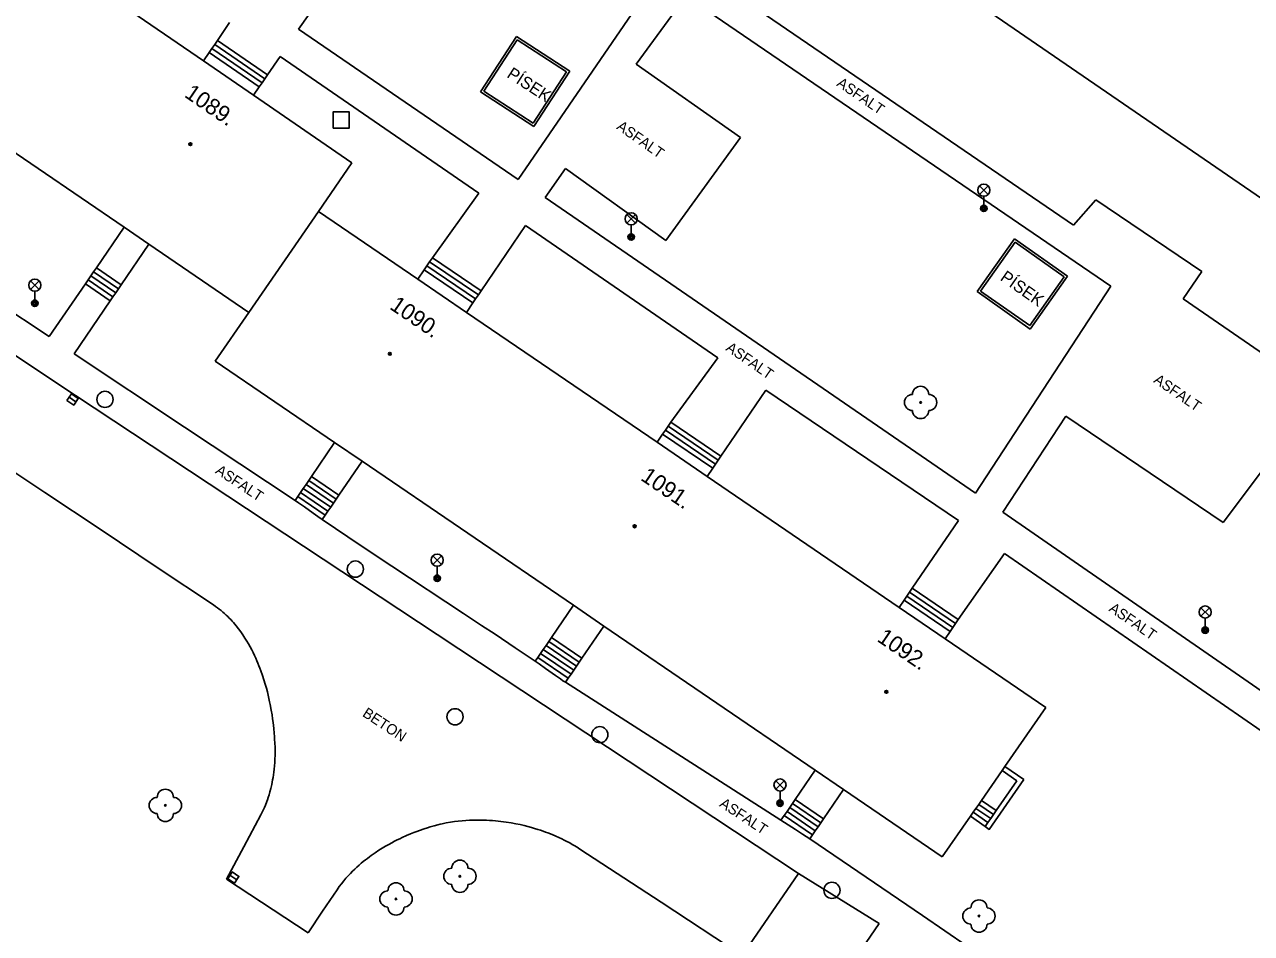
# Model space of a CAD drawing. Extents: x -539515 to -538098, y -1182060 to -1180157.
# Drawn here: x -538926.7 to -538850.8, y -1181479.7 to -1181423.5 of the extents above; entities that cross this region are included whole.
import ezdxf

# ---------------------------------------------------------------- set-up
doc = ezdxf.new("R2010")
doc.units = 0
for name, color, linetype in [('Vrstva 1', 7, 'Continuous'), ('Vrstva 13', 7, 'Continuous'), ('Vrstva 22', 7, 'Continuous'), ('Vrstva 26', 7, 'Continuous'), ('Vrstva 27', 7, 'Continuous'), ('Vrstva 33', 7, 'Continuous'), ('Vrstva 39', 7, 'Continuous'), ('Vrstva 40', 7, 'Continuous'), ('Vrstva 41', 7, 'Continuous'), ('Vrstva 47', 7, 'Continuous'), ('Vrstva 68', 7, 'Continuous'), ('Vrstva 88', 7, 'Continuous')]:
    doc.layers.add(name, color=color, linetype=linetype)

msp = doc.modelspace()

# ---------------------------------------------------------------- linework, layer by layer
at = {"layer": 'Vrstva 1'}
for p, q in [((-538934.28, -1181376.5), (-538829.84, -1181448.24)), ((-538906.43, -1181432.04), (-538908.499, -1181435.046)), ((-538908.499, -1181435.046), (-538912.8, -1181441.293)), ((-538914.87, -1181444.3), (-538912.8, -1181441.293))]:
    msp.add_line(p, q, dxfattribs=at)
for points in [[(-538906.43, -1181432.04), (-538912.507, -1181427.872), (-538915.603, -1181425.748), (-538927.397, -1181417.659), (-538930.405, -1181415.595), (-538942.269, -1181407.458), (-538945.22, -1181405.434), (-538951.32, -1181401.25)], [(-538912.8, -1181441.293), (-538918.981, -1181437.077), (-538920.514, -1181436.032), (-538933.82, -1181426.956), (-538935.618, -1181425.73), (-538948.631, -1181416.854), (-538950.43, -1181415.627), (-538957.77, -1181410.62)], [(-538908.499, -1181435.046), (-538902.354, -1181439.236), (-538899.343, -1181441.288), (-538887.562, -1181449.32), (-538884.465, -1181451.431), (-538872.589, -1181459.527), (-538869.747, -1181461.464), (-538863.52, -1181465.71)], [(-538914.87, -1181444.3), (-538907.493, -1181449.332), (-538905.797, -1181450.488), (-538892.73, -1181459.4), (-538890.849, -1181460.683), (-538877.787, -1181469.592), (-538876.041, -1181470.782), (-538869.93, -1181474.95)], [(-538869.93, -1181474.95), (-538868.192, -1181472.444), (-538868.02, -1181472.197), (-538867.849, -1181471.951), (-538867.678, -1181471.704), (-538867.507, -1181471.458), (-538866.229, -1181469.614), (-538866.058, -1181469.368), (-538863.52, -1181465.71)]]:
    msp.add_lwpolyline(points, dxfattribs=at)
at = {"layer": 'Vrstva 13'}
for p, q in [((-538921.75, -1181394.98), (-538861.81, -1181435.89)), ((-538901.08, -1181411.44), (-538909.72, -1181423.79)), ((-538896.14, -1181433.08), (-538887.57, -1181420.57)), ((-538888.85, -1181425.95), (-538885.78, -1181421.74)), ((-538885.78, -1181421.74), (-538859.506, -1181439.672)), ((-538914.74, -1181424.49), (-538913.99, -1181423.38)), ((-538896.14, -1181433.08), (-538909.72, -1181423.79)), ((-538911.813, -1181426.86), (-538914.909, -1181424.737)), ((-538911.644, -1181426.613), (-538914.74, -1181424.49)), ((-538912.152, -1181427.355), (-538915.248, -1181425.232)), ((-538911.983, -1181427.107), (-538915.079, -1181424.984)), ((-538911.644, -1181426.613), (-538910.86, -1181425.47)), ((-538910.86, -1181425.47), (-538898.57, -1181433.92)), ((-538882.41, -1181430.47), (-538888.85, -1181425.95)), ((-538887.02, -1181436.85), (-538882.41, -1181430.47)), ((-538894.48, -1181434.19), (-538893.22, -1181432.39)), ((-538893.22, -1181432.39), (-538887.02, -1181436.85)), ((-538925.14, -1181442.78), (-538938.59, -1181433.95)), ((-538898.57, -1181433.92), (-538901.45, -1181437.91)), ((-538867.88, -1181452.47), (-538894.48, -1181434.19)), ((-538861.81, -1181435.89), (-538860.44, -1181434.33)), ((-538860.44, -1181434.33), (-538853.874, -1181438.763)), ((-538898.439, -1181439.963), (-538895.69, -1181435.93)), ((-538895.69, -1181435.93), (-538883.81, -1181444.11)), ((-538898.777, -1181440.458), (-538901.788, -1181438.405)), ((-538898.608, -1181440.21), (-538901.619, -1181438.157)), ((-538898.439, -1181439.963), (-538901.45, -1181437.91)), ((-538921.028, -1181440.08), (-538922.561, -1181439.034)), ((-538920.859, -1181439.832), (-538922.392, -1181438.786)), ((-538920.69, -1181439.584), (-538922.223, -1181438.538)), ((-538898.946, -1181440.706), (-538901.957, -1181438.653)), ((-538853.874, -1181438.763), (-538855.04, -1181440.46)), ((-538922.9, -1181439.53), (-538925.14, -1181442.78)), ((-538921.367, -1181440.576), (-538922.9, -1181439.53)), ((-538921.197, -1181440.328), (-538922.73, -1181439.282)), ((-538859.506, -1181439.672), (-538867.88, -1181452.47)), ((-538921.367, -1181440.576), (-538923.6, -1181443.85)), ((-538855.04, -1181440.46), (-538826.77, -1181459.89)), ((-538923.6, -1181443.85), (-538916.77, -1181448.385)), ((-538883.81, -1181444.11), (-538886.71, -1181448.07)), ((-538883.613, -1181450.182), (-538880.83, -1181446.1)), ((-538880.83, -1181446.1), (-538868.93, -1181454.16)), ((-538883.613, -1181450.182), (-538886.71, -1181448.07)), ((-538862.3, -1181447.71), (-538866.18, -1181453.64)), ((-538852.56, -1181454.29), (-538862.3, -1181447.71)), ((-538847.88, -1181448.02), (-538852.56, -1181454.29)), ((-538916.77, -1181448.385), (-538909.94, -1181452.92)), ((-538884.12, -1181450.925), (-538887.217, -1181448.813)), ((-538883.951, -1181450.677), (-538887.048, -1181448.565)), ((-538883.782, -1181450.429), (-538886.879, -1181448.317)), ((-538907.566, -1181453.085), (-538909.262, -1181451.928)), ((-538907.397, -1181452.837), (-538909.093, -1181451.68)), ((-538907.228, -1181452.589), (-538908.924, -1181451.432)), ((-538908.074, -1181453.829), (-538909.77, -1181452.672)), ((-538907.904, -1181453.581), (-538909.6, -1181452.424)), ((-538907.735, -1181453.333), (-538909.431, -1181452.176)), ((-538868.93, -1181454.16), (-538871.782, -1181458.343)), ((-538866.18, -1181453.64), (-538836.02, -1181474.52)), ((-538868.94, -1181460.28), (-538866.08, -1181456.2)), ((-538866.08, -1181456.2), (-538813.97, -1181492.19)), ((-538903.962, -1181456.979), (-538899.518, -1181459.908)), ((-538872.119, -1181458.838), (-538869.277, -1181460.775)), ((-538871.95, -1181458.59), (-538869.108, -1181460.527)), ((-538871.782, -1181458.343), (-538868.94, -1181460.28)), ((-538872.288, -1181459.086), (-538869.446, -1181461.023)), ((-538894.423, -1181461.885), (-538892.542, -1181463.168)), ((-538894.254, -1181461.637), (-538892.373, -1181462.92)), ((-538894.085, -1181461.389), (-538892.204, -1181462.672)), ((-538894.931, -1181462.629), (-538893.05, -1181463.912)), ((-538894.761, -1181462.381), (-538892.88, -1181463.664)), ((-538894.592, -1181462.133), (-538892.711, -1181463.416)), ((-538893.22, -1181464.16), (-538886.56, -1181468.425)), ((-538886.56, -1181468.425), (-538879.9, -1181472.69)), ((-538879.188, -1181471.647), (-538877.442, -1181472.838)), ((-538879.019, -1181471.399), (-538877.273, -1181472.59)), ((-538867.678, -1181471.704), (-538866.763, -1181472.339)), ((-538867.507, -1181471.458), (-538866.592, -1181472.093)), ((-538879.696, -1181472.391), (-538877.95, -1181473.582)), ((-538879.526, -1181472.143), (-538877.78, -1181473.334)), ((-538879.357, -1181471.895), (-538877.611, -1181473.086)), ((-538868.192, -1181472.444), (-538867.277, -1181473.079)), ((-538868.02, -1181472.197), (-538867.105, -1181472.832)), ((-538867.849, -1181471.951), (-538866.934, -1181472.586)), ((-538878.12, -1181473.83), (-538871.16, -1181478.58)), ((-538878.81, -1181475.98), (-538873.83, -1181479.06)), ((-538871.16, -1181478.58), (-538864.2, -1181483.33)), ((-538873.83, -1181479.06), (-538885.11, -1181495.47))]:
    msp.add_line(p, q, dxfattribs=at)
for points in [[(-538915.603, -1181425.748), (-538915.248, -1181425.232), (-538915.079, -1181424.984), (-538914.909, -1181424.737), (-538914.74, -1181424.49)], [(-538912.507, -1181427.872), (-538912.152, -1181427.355), (-538911.983, -1181427.107), (-538911.813, -1181426.86), (-538911.644, -1181426.613)], [(-538920.514, -1181436.032), (-538922.223, -1181438.538), (-538922.392, -1181438.786), (-538922.561, -1181439.034), (-538922.73, -1181439.282), (-538922.9, -1181439.53)], [(-538918.981, -1181437.077), (-538920.69, -1181439.584), (-538920.859, -1181439.832), (-538921.028, -1181440.08), (-538921.197, -1181440.328), (-538921.367, -1181440.576)], [(-538902.354, -1181439.236), (-538901.957, -1181438.653), (-538901.788, -1181438.405), (-538901.619, -1181438.157), (-538901.45, -1181437.91)], [(-538899.343, -1181441.288), (-538898.946, -1181440.706), (-538898.777, -1181440.458), (-538898.608, -1181440.21), (-538898.439, -1181439.963)], [(-538887.562, -1181449.32), (-538887.217, -1181448.813), (-538887.048, -1181448.565), (-538886.879, -1181448.317), (-538886.71, -1181448.07)], [(-538907.493, -1181449.332), (-538908.924, -1181451.432), (-538909.093, -1181451.68), (-538909.262, -1181451.928), (-538909.431, -1181452.176), (-538909.6, -1181452.424), (-538909.77, -1181452.672), (-538909.94, -1181452.92)], [(-538905.797, -1181450.488), (-538907.228, -1181452.589), (-538907.397, -1181452.837), (-538907.566, -1181453.085), (-538907.735, -1181453.333), (-538907.904, -1181453.581), (-538908.074, -1181453.829), (-538908.26, -1181454.1)], [(-538884.465, -1181451.431), (-538884.12, -1181450.925), (-538883.951, -1181450.677), (-538883.782, -1181450.429), (-538883.613, -1181450.182)], [(-538909.94, -1181452.92), (-538909.727, -1181453.064), (-538909.359, -1181453.321), (-538908.812, -1181453.713), (-538908.537, -1181453.908), (-538908.26, -1181454.1), (-538907.442, -1181454.655), (-538906.674, -1181455.173), (-538905.229, -1181456.139), (-538903.962, -1181456.979)], [(-538872.589, -1181459.527), (-538872.288, -1181459.086), (-538872.119, -1181458.838), (-538871.95, -1181458.59), (-538871.782, -1181458.343)], [(-538892.73, -1181459.4), (-538894.085, -1181461.389), (-538894.254, -1181461.637), (-538894.423, -1181461.885), (-538894.592, -1181462.133), (-538894.761, -1181462.381), (-538894.931, -1181462.629), (-538895.09, -1181462.86)], [(-538899.518, -1181459.908), (-538898.408, -1181460.641), (-538897.576, -1181461.193), (-538896.331, -1181462.024), (-538895.09, -1181462.86), (-538894.855, -1181463.021), (-538894.449, -1181463.309), (-538893.84, -1181463.742), (-538893.532, -1181463.954), (-538893.377, -1181464.058), (-538893.22, -1181464.16)], [(-538869.747, -1181461.464), (-538869.446, -1181461.023), (-538869.277, -1181460.775), (-538869.108, -1181460.527), (-538868.94, -1181460.28)], [(-538890.849, -1181460.683), (-538892.204, -1181462.672), (-538892.373, -1181462.92), (-538892.542, -1181463.168), (-538892.711, -1181463.416), (-538892.88, -1181463.664), (-538893.05, -1181463.912), (-538893.22, -1181464.16)], [(-538877.787, -1181469.592), (-538879.019, -1181471.399), (-538879.188, -1181471.647), (-538879.357, -1181471.895), (-538879.526, -1181472.143), (-538879.696, -1181472.391), (-538879.9, -1181472.69)], [(-538876.041, -1181470.782), (-538877.273, -1181472.59), (-538877.442, -1181472.838), (-538877.611, -1181473.086), (-538877.78, -1181473.334), (-538877.95, -1181473.582), (-538878.12, -1181473.83)], [(-538879.9, -1181472.69), (-538879.006, -1181473.254), (-538878.56, -1181473.538), (-538878.339, -1181473.683), (-538878.12, -1181473.83)]]:
    msp.add_lwpolyline(points, dxfattribs=at)
at = {"layer": 'Vrstva 22'}
for centre in [(-538871.27, -1181446.86), (-538917.96, -1181471.77), (-538899.75, -1181476.15), (-538903.7, -1181477.55), (-538867.66, -1181478.61)]:
    msp.add_circle(centre, 0.05, dxfattribs=at)
for centre, start, end in [((-538871.27, -1181446.36), 0, 180), ((-538871.77, -1181446.86), 90, 270), ((-538870.77, -1181446.86), 270, 90), ((-538871.27, -1181447.36), 180, 0), ((-538917.96, -1181471.27), 0, 180), ((-538918.46, -1181471.77), 90, 270), ((-538917.46, -1181471.77), 270, 90), ((-538917.96, -1181472.27), 180, 0), ((-538899.75, -1181475.65), 0, 180), ((-538900.25, -1181476.15), 90, 270), ((-538899.25, -1181476.15), 270, 90), ((-538904.2, -1181477.55), 90, 270), ((-538903.7, -1181477.05), 0, 180), ((-538903.2, -1181477.55), 270, 90), ((-538899.75, -1181476.65), 180, 0), ((-538867.66, -1181478.11), 0, 180), ((-538903.7, -1181478.05), 180, 0), ((-538868.16, -1181478.61), 90, 270), ((-538867.16, -1181478.61), 270, 90), ((-538867.66, -1181479.11), 180, 0)]:
    msp.add_arc(centre, 0.5, start, end, dxfattribs=at)
at = {"layer": 'Vrstva 26'}
msp.add_lwpolyline([(-538907.59, -1181429.9), (-538906.59, -1181429.9), (-538906.59, -1181428.9), (-538907.59, -1181428.9)], close=True, dxfattribs=at)
at = {"layer": 'Vrstva 27'}
for p, q in [((-538923.905, -1181446.539), (-538923.487, -1181446.815)), ((-538913.966, -1181476.089), (-538913.548, -1181476.365))]:
    msp.add_line(p, q, dxfattribs=at)
for points in [[(-538924.042, -1181446.748), (-538923.625, -1181447.023), (-538923.35, -1181446.606), (-538923.767, -1181446.331)], [(-538914.103, -1181476.298), (-538913.686, -1181476.573), (-538913.411, -1181476.156), (-538913.828, -1181475.881)]]:
    msp.add_lwpolyline(points, close=True, dxfattribs=at)
for centre in [(-538921.69, -1181446.67), (-538906.21, -1181457.16), (-538900.05, -1181466.29), (-538891.1, -1181467.4), (-538876.75, -1181477.02)]:
    msp.add_circle(centre, 0.5, dxfattribs=at)
at = {"layer": 'Vrstva 33'}
for p, q in [((-538867.625, -1181434), (-538867.095, -1181433.47)), ((-538867.625, -1181433.47), (-538867.095, -1181434)), ((-538867.36, -1181434.11), (-538867.36, -1181434.86)), ((-538889.425, -1181435.77), (-538888.895, -1181435.24)), ((-538889.425, -1181435.24), (-538888.895, -1181435.77)), ((-538889.16, -1181435.88), (-538889.16, -1181436.63)), ((-538926.295, -1181439.87), (-538925.765, -1181439.34)), ((-538926.295, -1181439.34), (-538925.765, -1181439.87)), ((-538926.03, -1181439.98), (-538926.03, -1181440.73)), ((-538901.415, -1181456.87), (-538900.885, -1181456.34)), ((-538901.415, -1181456.34), (-538900.885, -1181456.87)), ((-538901.15, -1181456.98), (-538901.15, -1181457.73)), ((-538853.945, -1181460.08), (-538853.415, -1181459.55)), ((-538853.945, -1181459.55), (-538853.415, -1181460.08)), ((-538853.68, -1181460.19), (-538853.68, -1181460.94)), ((-538880.225, -1181470.77), (-538879.695, -1181470.24)), ((-538880.225, -1181470.24), (-538879.695, -1181470.77)), ((-538879.96, -1181470.88), (-538879.96, -1181471.63))]:
    msp.add_line(p, q, dxfattribs=at)
for centre, radius in [((-538867.36, -1181433.735), 0.375), ((-538889.16, -1181435.505), 0.375), ((-538867.36, -1181434.86), 0.2), ((-538867.36, -1181434.86), 0.145), ((-538867.36, -1181434.86), 0.0876), ((-538889.16, -1181436.63), 0.2), ((-538889.16, -1181436.63), 0.145), ((-538889.16, -1181436.63), 0.0876), ((-538926.03, -1181439.605), 0.375), ((-538926.03, -1181440.73), 0.2), ((-538926.03, -1181440.73), 0.145), ((-538926.03, -1181440.73), 0.0876), ((-538901.15, -1181456.605), 0.375), ((-538901.15, -1181457.73), 0.2), ((-538901.15, -1181457.73), 0.145), ((-538901.15, -1181457.73), 0.0876), ((-538853.68, -1181459.815), 0.375), ((-538853.68, -1181460.94), 0.2), ((-538853.68, -1181460.94), 0.145), ((-538853.68, -1181460.94), 0.0876), ((-538879.96, -1181470.505), 0.375), ((-538879.96, -1181471.63), 0.2), ((-538879.96, -1181471.63), 0.145), ((-538879.96, -1181471.63), 0.0876)]:
    msp.add_circle(centre, radius, dxfattribs=at)
at = {"layer": 'Vrstva 39'}
for centre, radius in [((-538916.414, -1181430.894), 0.09), ((-538916.414, -1181430.894), 0.0398), ((-538904.079, -1181443.851), 0.09), ((-538904.079, -1181443.851), 0.0398), ((-538888.946, -1181454.513), 0.09), ((-538888.946, -1181454.513), 0.0398), ((-538873.387, -1181464.749), 0.09), ((-538873.387, -1181464.749), 0.0398)]:
    msp.add_circle(centre, radius, dxfattribs=at)
at = {"layer": 'Vrstva 68'}
for p, q in [((-538866.058, -1181469.368), (-538864.896, -1181470.175)), ((-538866.229, -1181469.614), (-538865.313, -1181470.25))]:
    msp.add_line(p, q, dxfattribs=at)
for points in [[(-538864.896, -1181470.175), (-538867.03, -1181473.25), (-538867.277, -1181473.079)], [(-538865.313, -1181470.25), (-538866.592, -1181472.093), (-538866.763, -1181472.339), (-538866.934, -1181472.586), (-538867.105, -1181472.832), (-538867.277, -1181473.079)]]:
    msp.add_lwpolyline(points, dxfattribs=at)
at = {"layer": 'Vrstva 88'}
for p, q in [((-538898.473, -1181427.66), (-538896.25, -1181424.24)), ((-538898.265, -1181427.616), (-538896.206, -1181424.448)), ((-538896.25, -1181424.24), (-538892.957, -1181426.38)), ((-538896.206, -1181424.448), (-538893.165, -1181426.424)), ((-538893.165, -1181426.424), (-538895.224, -1181429.592)), ((-538892.957, -1181426.38), (-538895.18, -1181429.8)), ((-538895.18, -1181429.8), (-538898.473, -1181427.66)), ((-538895.224, -1181429.592), (-538898.265, -1181427.616)), ((-538867.77, -1181440.01), (-538865.466, -1181436.738)), ((-538865.466, -1181436.738), (-538862.186, -1181439.048)), ((-538867.561, -1181439.974), (-538865.43, -1181436.947)), ((-538865.43, -1181436.947), (-538862.395, -1181439.084)), ((-538862.395, -1181439.084), (-538864.526, -1181442.111)), ((-538862.186, -1181439.048), (-538864.49, -1181442.32)), ((-538864.49, -1181442.32), (-538867.77, -1181440.01)), ((-538864.526, -1181442.111), (-538867.561, -1181439.974)), ((-538923.52, -1181446.42), (-538932.1, -1181440.742)), ((-538901.165, -1181461.2), (-538923.52, -1181446.42)), ((-538878.81, -1181475.98), (-538901.165, -1181461.2)), ((-538892.33, -1181474.47), (-538887.31, -1181477.76)), ((-538914.18, -1181476.32), (-538909.14, -1181479.64)), ((-538882.29, -1181481.05), (-538878.81, -1181475.98)), ((-538887.31, -1181477.76), (-538882.29, -1181481.05))]:
    msp.add_line(p, q, dxfattribs=at)
for points in [[(-538928.89, -1181450.1), (-538927.757, -1181450.856), (-538925.412, -1181452.42), (-538921.935, -1181454.74), (-538918.458, -1181457.06)], [(-538918.458, -1181457.06), (-538914.98, -1181459.38), (-538914.857, -1181459.465), (-538914.738, -1181459.551), (-538914.623, -1181459.639), (-538914.512, -1181459.728), (-538914.404, -1181459.818), (-538914.301, -1181459.909), (-538914.201, -1181460.001), (-538914.104, -1181460.094), (-538914.01, -1181460.188), (-538913.92, -1181460.282), (-538913.832, -1181460.376), (-538913.748, -1181460.471), (-538913.666, -1181460.566), (-538913.587, -1181460.661), (-538913.436, -1181460.852), (-538913.295, -1181461.043), (-538913.163, -1181461.233), (-538913.04, -1181461.421), (-538912.924, -1181461.606), (-538912.816, -1181461.79), (-538912.716, -1181461.971), (-538912.621, -1181462.148), (-538912.533, -1181462.323), (-538912.451, -1181462.494), (-538912.373, -1181462.662), (-538912.301, -1181462.826), (-538912.233, -1181462.986), (-538912.17, -1181463.143), (-538912.11, -1181463.295), (-538912.055, -1181463.444), (-538911.952, -1181463.735), (-538911.862, -1181464.011), (-538911.783, -1181464.271), (-538911.714, -1181464.516), (-538911.653, -1181464.747), (-538911.6, -1181464.964), (-538911.553, -1181465.168), (-538911.511, -1181465.359), (-538911.474, -1181465.538), (-538911.412, -1181465.874), (-538911.363, -1181466.167), (-538911.326, -1181466.423), (-538911.296, -1181466.645), (-538911.273, -1181466.839), (-538911.255, -1181467.008), (-538911.228, -1181467.301), (-538911.211, -1181467.519), (-538911.201, -1181467.681), (-538911.188, -1181467.922), (-538911.18, -1181468.16)], [(-538911.18, -1181468.16), (-538911.176, -1181468.42), (-538911.178, -1181468.668), (-538911.186, -1181468.902)], [(-538911.186, -1181468.902), (-538911.198, -1181469.123), (-538911.214, -1181469.331), (-538911.233, -1181469.526), (-538911.254, -1181469.71), (-538911.278, -1181469.882), (-538911.302, -1181470.044), (-538911.328, -1181470.195), (-538911.355, -1181470.336), (-538911.382, -1181470.468), (-538911.438, -1181470.715), (-538911.493, -1181470.929), (-538911.546, -1181471.114), (-538911.597, -1181471.275), (-538911.643, -1181471.415), (-538911.687, -1181471.536), (-538911.767, -1181471.745), (-538911.832, -1181471.9), (-538911.883, -1181472.014), (-538911.964, -1181472.184), (-538912.05, -1181472.35), (-538913.115, -1181474.335), (-538914.18, -1181476.32)], [(-538909.14, -1181479.64), (-538908.24, -1181478.31), (-538907.34, -1181476.98), (-538907.207, -1181476.79), (-538907.072, -1181476.61), (-538906.935, -1181476.439), (-538906.798, -1181476.277), (-538906.66, -1181476.123), (-538906.523, -1181475.976), (-538906.386, -1181475.837), (-538906.25, -1181475.705), (-538906.116, -1181475.58), (-538905.983, -1181475.461), (-538905.851, -1181475.348), (-538905.722, -1181475.24), (-538905.594, -1181475.138), (-538905.469, -1181475.041), (-538905.346, -1181474.948), (-538905.225, -1181474.86), (-538904.988, -1181474.695), (-538904.761, -1181474.545), (-538904.545, -1181474.409), (-538904.339, -1181474.287), (-538904.145, -1181474.176), (-538903.96, -1181474.075), (-538903.786, -1181473.983), (-538903.622, -1181473.9), (-538903.467, -1181473.825), (-538903.321, -1181473.756), (-538903.046, -1181473.632), (-538902.805, -1181473.53), (-538902.592, -1181473.445), (-538902.406, -1181473.374), (-538902.244, -1181473.315), (-538901.959, -1181473.217)], [(-538901.959, -1181473.217), (-538901.746, -1181473.149), (-538901.586, -1181473.1), (-538901.347, -1181473.032), (-538901.11, -1181472.97), (-538900.979, -1181472.938), (-538900.85, -1181472.909), (-538900.591, -1181472.856), (-538900.338, -1181472.811), (-538900.09, -1181472.774), (-538899.847, -1181472.744), (-538899.609, -1181472.72), (-538899.377, -1181472.701), (-538899.151, -1181472.689), (-538898.931, -1181472.681), (-538898.716, -1181472.677), (-538898.508, -1181472.677), (-538898.305, -1181472.681), (-538898.108, -1181472.688), (-538897.917, -1181472.698), (-538897.732, -1181472.71), (-538897.552, -1181472.725), (-538897.378, -1181472.742), (-538897.209, -1181472.761), (-538897.046, -1181472.782), (-538896.888, -1181472.804), (-538896.582, -1181472.852), (-538896.296, -1181472.904), (-538896.029, -1181472.959), (-538895.78, -1181473.016), (-538895.547, -1181473.074), (-538895.331, -1181473.133), (-538895.129, -1181473.191), (-538894.941, -1181473.249), (-538894.766, -1181473.306), (-538894.603, -1181473.362), (-538894.451, -1181473.416), (-538894.31, -1181473.469), (-538894.047, -1181473.573), (-538893.821, -1181473.669), (-538893.625, -1181473.757), (-538893.456, -1181473.836), (-538893.309, -1181473.908), (-538893.182, -1181473.973), (-538892.963, -1181474.09), (-538892.801, -1181474.181), (-538892.681, -1181474.251), (-538892.504, -1181474.359), (-538892.33, -1181474.47)]]:
    msp.add_lwpolyline(points, dxfattribs=at)

# ---------------------------------------------------------------- texts
at = {"layer": 'Vrstva 40'}
for s, rotation, p in [('ASFALT', 325.68584, (-538876.505, -1181427.249)), ('ASFALT', 324.93639, (-538890.11, -1181429.919)), ('ASFALT', 325.50245, (-538883.359, -1181443.607)), ('ASFALT', 325.49922, (-538856.914, -1181445.588)), ('ASFALT', 326.52933, (-538914.915, -1181451.201)), ('ASFALT', 325.36893, (-538859.679, -1181459.716)), ('BETON', 326.52933, (-538905.825, -1181466.217)), ('ASFALT', 326.52933, (-538883.751, -1181471.795))]:
    msp.add_text(s, height=0.65, rotation=rotation, dxfattribs=at).set_placement(p)
at = {"layer": 'Vrstva 41'}
for rotation, p in [(326.98474, (-538896.9, -1181426.719)), (324.84418, (-538866.403, -1181439.266))]:
    msp.add_text('PÍSEK', height=0.75, rotation=rotation, dxfattribs=at).set_placement(p)
at = {"layer": 'Vrstva 47'}
for s, rotation, p in [('1089.', 325.55382, (-538916.837, -1181427.933)), ('1090.', 325.71617, (-538904.15, -1181441.037)), ('1091.', 325.71617, (-538888.635, -1181451.615)), ('1092.', 325.71617, (-538874.016, -1181461.581))]:
    msp.add_text(s, height=1, rotation=rotation, dxfattribs=at).set_placement(p)

doc.saveas('drawing.dxf')
